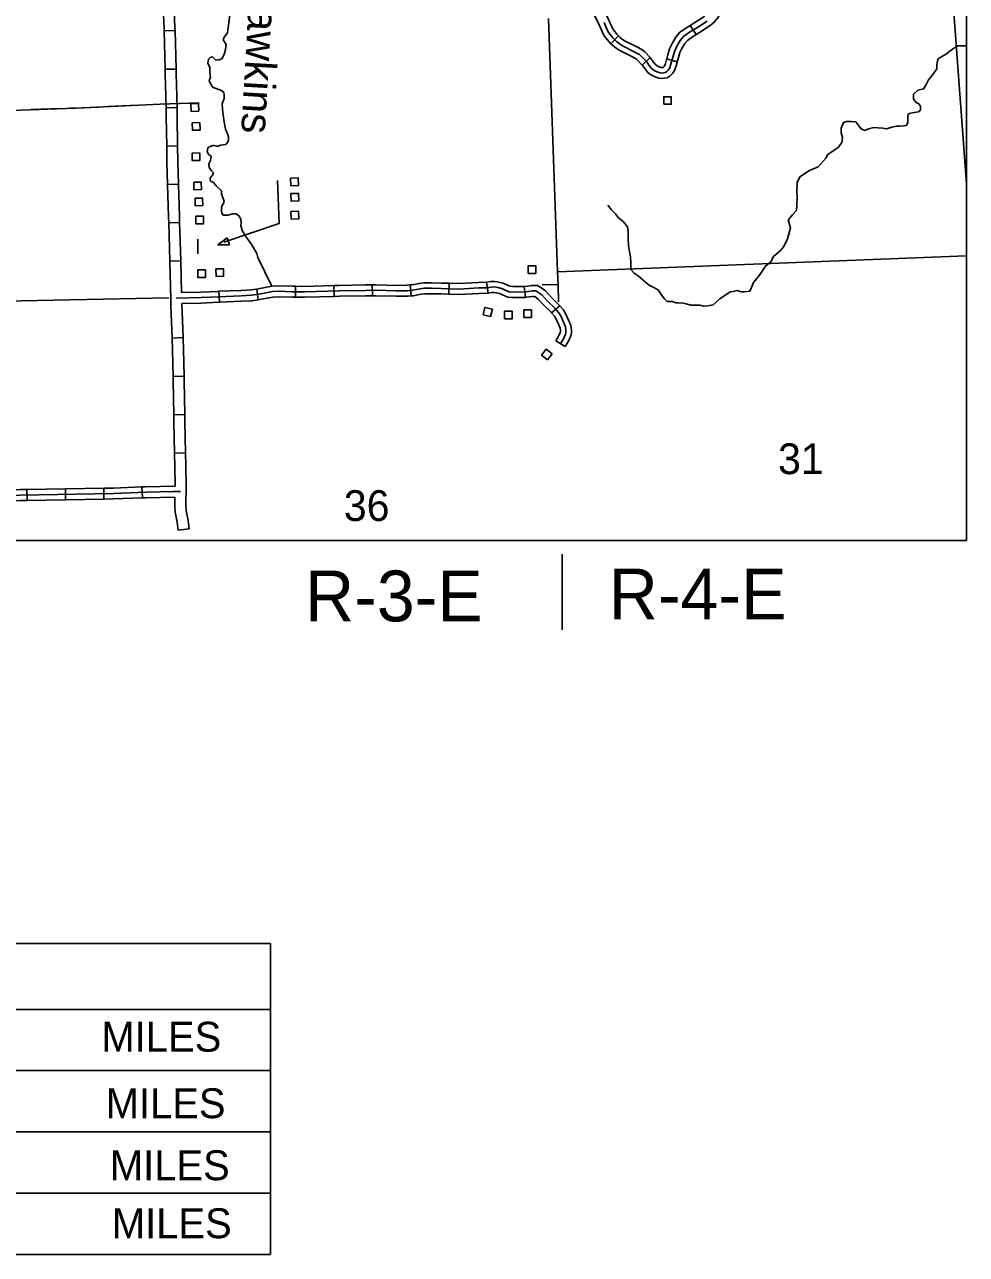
# Model space of a CAD drawing. Extents: x 155 to 3386, y 68 to 2138.
# Drawn here: x 1972.1 to 2342.2, y 68.1 to 551.2 of the extents above; entities that cross this region are included whole.
import ezdxf

# ---------------------------------------------------------------- set-up
doc = ezdxf.new("R2010")
doc.units = 0
for name, color, linetype in [('2', 7, 'Continuous'), ('3', 7, 'Continuous'), ('Default', 7, 'Continuous'), ('E_No Plot', 7, 'Continuous'), ('Level 32', 7, 'Continuous'), ('Level 35', 7, 'Continuous'), ('Level 4', 7, 'Continuous'), ('Level 43', 7, 'Continuous'), ('Level 5', 7, 'Continuous'), ('Level 56', 7, 'Continuous')]:
    doc.layers.add(name, color=color, linetype=linetype)

msp = doc.modelspace()

# ---------------------------------------------------------------- linework, layer by layer
at = {"layer": '2'}
msp.add_line((2183.32, 343.22), (2183.32, 313.48), dxfattribs=at)
at = {"layer": '3'}
for p, q in [((1431.26, 190.26), (2068.72, 190.26)), ((2068.72, 190.26), (2068.72, 68.06)), ((1431.26, 164.33), (2068.72, 164.33)), ((1431.26, 140.26), (2068.72, 140.26)), ((1431.26, 116.19), (2068.72, 116.19)), ((1431.26, 92.13), (2068.72, 92.13)), ((1431.26, 68.06), (2068.72, 68.06))]:
    msp.add_line(p, q, dxfattribs=at)
at = {"layer": 'Default'}
msp.add_lwpolyline([(1150.5, 1308.99), (2342.15, 1308.99), (2342.15, 348.58), (1150.5, 348.58)], close=True, dxfattribs=at)
at = {"layer": 'E_No Plot'}
msp.add_lwpolyline([(1150.5, 1308.99), (2342.15, 1308.99), (2342.15, 348.58), (1150.5, 348.58)], close=True, dxfattribs=at)
msp.add_lwpolyline([(1150.5, 1308.99), (2342.15, 1308.99), (2342.15, 348.58), (1150.5, 348.58)], close=True, dxfattribs=at)
at = {"layer": 'Level 32'}
for p, q in [((2233.63, 550.92), (2235.92, 547.3)), ((2031.17, 548.86), (2026.89, 548.75)), ((2205.49, 546.76), (2202.46, 543.73)), ((2217.87, 538.29), (2214.75, 535.35)), ((2224.42, 537.77), (2228.55, 536.63)), ((2031.58, 533.78), (2027.29, 533.67)), ((2031.95, 518.69), (2027.66, 518.59)), ((2032.18, 503.59), (2027.9, 503.53)), ((2032.52, 488.54), (2028.24, 488.41)), ((2032.98, 473.47), (2028.69, 473.33)), ((2033.46, 458.37), (2029.18, 458.27)), ((2138.86, 449.59), (2138.71, 445.31)), ((2153.54, 450), (2154.17, 445.76)), ((2048.42, 446.44), (2048.6, 442.15)), ((2063.26, 447.33), (2063.85, 443.09)), ((2078.56, 448.43), (2078.5, 444.14)), ((2093.54, 448.73), (2093.68, 444.45)), ((2108.67, 448.99), (2108.71, 444.71)), ((2123.59, 448.94), (2123.95, 444.67)), ((2168.32, 448.34), (2168.86, 444.09)), ((2182.39, 440.8), (2179.17, 437.97)), ((2034.34, 428.25), (2030.06, 428.08)), ((2184.53, 424.76), (2180.83, 426.94)), ((2034.73, 413.12), (2030.44, 413.04)), ((2034.99, 398.04), (2030.7, 397.96)), ((2035.29, 382.96), (2031, 382.87)), ((1973, 368.61), (1973.07, 364.32)), ((1988.08, 368.85), (1988.15, 364.56)), ((2003.17, 369.09), (2003.23, 364.8)), ((2018.19, 369.58), (2018.36, 365.3)), ((2036.69, 353.1), (2032.43, 352.61))]:
    msp.add_line(p, q, dxfattribs=at)
for points in [[(2026.89, 548.75), (2026.86, 549.77), (2026.28, 563.67), (2026.28, 563.66)], [(2031.17, 548.86), (2031.14, 549.92), (2030.55, 563.98), (2030.54, 564.09)], [(2243.15, 560.54), (2242.85, 559.93), (2240.88, 556.31), (2239.95, 555.17), (2238.93, 554.26), (2235.01, 551.79), (2233.63, 550.92)], [(2205.49, 546.76), (2204.82, 547.43), (2203.42, 549.2), (2202.85, 550.31), (2201.7, 552.95), (2200.38, 555.79), (2199.44, 557.19), (2198.57, 558.1), (2197.79, 558.63), (2196.16, 559.31), (2195.95, 559.36)], [(2247, 558.65), (2246.66, 557.97), (2244.46, 553.91), (2243.05, 552.19), (2241.51, 550.82), (2237.3, 548.17), (2235.92, 547.3)], [(2202.46, 543.73), (2201.61, 544.57), (2199.79, 546.87), (2198.97, 548.48), (2197.79, 551.2), (2196.64, 553.67), (2196.09, 554.49), (2195.78, 554.82), (2195.73, 554.85), (2194.88, 555.2), (2195.08, 555.16)], [(2240.22, 552.54), (2236.16, 549.98), (2233.38, 548.22), (2231.03, 546.61), (2229.72, 545), (2228.4, 542.81), (2227.52, 540.98), (2226.94, 538.85), (2226.42, 536.98), (2225.91, 535.26), (2225.44, 533.98), (2225, 533.36), (2224.41, 532.77), (2223.79, 532.37), (2223.06, 532.26), (2222.36, 532.19), (2221.81, 532.26), (2220.86, 532.55), (2219.51, 533.21), (2218.45, 533.95), (2217.46, 535.23), (2216.4, 536.73), (2214.28, 538.97), (2213.75, 539.43), (2211.92, 540.42), (2206.98, 542.91), (2205.78, 543.69), (2204.61, 544.61), (2203.21, 546), (2201.6, 548.03), (2200.91, 549.39), (2199.75, 552.08)], [(2233.63, 550.92), (2232.2, 550.01), (2229.57, 548.21), (2227.96, 546.24), (2226.51, 543.82), (2225.51, 541.73), (2224.87, 539.42), (2224.42, 537.77)], [(2027.29, 533.67), (2026.89, 548.75)], [(2031.58, 533.78), (2031.17, 548.86)], [(2217.87, 538.29), (2215.77, 540.52), (2214.98, 541.2), (2212.92, 542.32), (2208.05, 544.77), (2207.02, 545.44), (2206.03, 546.22), (2205.49, 546.76)], [(2235.92, 547.3), (2234.56, 546.43), (2232.5, 545.02), (2231.47, 543.77), (2230.29, 541.79), (2229.54, 540.22), (2229, 538.28), (2228.55, 536.63)], [(2214.75, 535.35), (2212.8, 537.42), (2212.53, 537.65), (2210.93, 538.52), (2205.91, 541.05), (2204.53, 541.95), (2203.18, 543), (2202.46, 543.73)], [(2228.55, 536.63), (2228.48, 536.4), (2227.94, 534.58), (2227.35, 532.98), (2226.64, 531.97), (2225.77, 531.1), (2224.56, 530.32), (2223.33, 530.14), (2222.33, 530.03), (2221.35, 530.16), (2220.07, 530.56), (2218.42, 531.36), (2216.95, 532.37), (2215.73, 533.95), (2214.73, 535.37), (2214.75, 535.35)], [(2224.42, 537.77), (2224.36, 537.57), (2223.88, 535.94), (2223.52, 534.99), (2223.35, 534.75), (2223.06, 534.45), (2223.01, 534.42), (2222.79, 534.39), (2222.39, 534.35), (2222.27, 534.36), (2221.65, 534.55), (2220.59, 535.07), (2219.94, 535.52), (2219.18, 536.5), (2218.06, 538.09), (2217.87, 538.29)], [(2027.66, 518.59), (2027.34, 531.86), (2027.29, 533.67)], [(2031.95, 518.69), (2031.63, 531.97), (2031.58, 533.78)], [(2027.9, 503.53), (2027.75, 514.99), (2027.66, 518.59)], [(2032.18, 503.59), (2032.03, 515.06), (2031.95, 518.69)], [(2028.24, 488.41), (2027.98, 497.18), (2027.9, 503.53)], [(2032.52, 488.54), (2032.26, 497.27), (2032.18, 503.59)], [(2028.69, 473.33), (2028.62, 475.77), (2028.24, 488.41)], [(2032.98, 473.47), (2032.9, 475.9), (2032.52, 488.54)], [(2029.18, 458.27), (2029.18, 458.4), (2028.69, 473.33)], [(2033.46, 458.37), (2033.46, 458.52), (2032.98, 473.47)], [(2029.5, 443.19), (2029.18, 458.27)], [(2033.73, 445.98), (2033.46, 458.37)], [(2138.86, 449.59), (2135.84, 449.7), (2131.96, 449.81), (2128.97, 449.77), (2127.22, 449.54), (2124.18, 448.99), (2123.59, 448.94)], [(2153.58, 450.01), (2150.41, 449.91), (2142.71, 449.46), (2138.86, 449.59)], [(2168.32, 448.34), (2168.3, 448.34), (2163.94, 448.31), (2162.96, 448.41), (2162.31, 448.64), (2160.13, 449.62), (2158.38, 450.08), (2156.82, 450.3), (2155.23, 450.25), (2153.54, 450)], [(2182.68, 425.85), (2183.83, 427.8), (2184.63, 429.65), (2184.77, 430.35), (2184.77, 431.04), (2184.6, 432.47), (2183.86, 434.32), (2182.75, 436.76), (2181.98, 438.01), (2180.49, 439.72), (2177.63, 442.51), (2175.33, 445.01), (2173.8, 446.13), (2172.96, 446.58), (2172.51, 446.62), (2171.54, 446.62), (2170.11, 446.41), (2168.44, 446.2), (2163.84, 446.16), (2162.48, 446.3), (2161.51, 446.65), (2159.42, 447.59), (2157.96, 447.98), (2156.7, 448.15), (2155.41, 448.11), (2153.78, 447.87), (2150.5, 447.77), (2142.74, 447.31), (2135.77, 447.56), (2131.94, 447.66), (2129.12, 447.63), (2127.56, 447.42), (2124.46, 446.86), (2122.4, 446.69), (2118.05, 446.65), (2110.04, 446.86), (2106.04, 446.83), (2095.69, 446.65), (2082.04, 446.23), (2077.31, 446.3), (2071.84, 446.44), (2069.51, 446.34), (2067.66, 446.02), (2064.14, 445.29), (2061.15, 444.87), (2057.21, 444.67), (2048.19, 444.28), (2041.44, 443.97), (2031.63, 443.8)], [(2048.42, 446.44), (2048.1, 446.42), (2041.37, 446.11), (2033.73, 445.98)], [(2063.26, 447.33), (2060.94, 447.01), (2057.11, 446.81), (2048.42, 446.44)], [(2078.56, 448.43), (2077.35, 448.45), (2071.82, 448.59), (2069.28, 448.47), (2067.26, 448.13), (2063.78, 447.41), (2063.26, 447.33)], [(2093.54, 448.73), (2082.03, 448.38), (2078.56, 448.43)], [(2108.67, 448.99), (2106.01, 448.97), (2095.64, 448.79), (2093.54, 448.73)], [(2108.71, 444.71), (2106.06, 444.68), (2095.74, 444.51), (2093.68, 444.45)], [(2123.59, 448.94), (2122.3, 448.83), (2118.07, 448.79), (2110.06, 449), (2108.67, 448.99)], [(2123.95, 444.67), (2122.5, 444.54), (2118.03, 444.51), (2110.02, 444.72), (2108.71, 444.71)], [(2138.71, 445.31), (2135.71, 445.42), (2131.93, 445.52), (2129.28, 445.49), (2127.89, 445.3), (2124.74, 444.73), (2123.95, 444.67)], [(2154.17, 445.76), (2153.97, 445.73), (2150.6, 445.63), (2142.76, 445.17), (2138.71, 445.31)], [(2168.86, 444.09), (2168.58, 444.06), (2163.74, 444.02), (2162.01, 444.2), (2160.71, 444.66), (2158.7, 445.56), (2157.54, 445.87), (2156.58, 446), (2155.6, 445.98), (2154.17, 445.76)], [(2182.39, 440.8), (2182.04, 441.19), (2179.17, 444), (2176.77, 446.62), (2174.95, 447.95), (2173.58, 448.68), (2172.59, 448.76), (2171.38, 448.76), (2169.82, 448.53), (2168.32, 448.34)], [(2030.06, 428.08), (2029.56, 440.75), (2029.5, 443.19)], [(2048.6, 442.15), (2048.29, 442.14), (2041.51, 441.83), (2033.81, 441.69)], [(2034.34, 428.25), (2033.81, 441.69)], [(2063.85, 443.09), (2061.35, 442.74), (2057.32, 442.53), (2048.6, 442.15)], [(2078.5, 444.14), (2077.26, 444.16), (2071.86, 444.3), (2069.73, 444.2), (2068.06, 443.92), (2064.51, 443.18), (2063.85, 443.09)], [(2093.68, 444.45), (2082.06, 444.09), (2078.5, 444.14)], [(2179.17, 437.97), (2178.93, 438.24), (2176.09, 441.01), (2173.9, 443.41), (2172.65, 444.31), (2172.36, 444.47), (2171.69, 444.47), (2170.4, 444.28), (2168.86, 444.09)], [(2184.53, 424.76), (2185.74, 426.83), (2186.69, 429.01), (2186.91, 430.13), (2186.91, 431.17), (2186.69, 433), (2185.84, 435.16), (2184.65, 437.76), (2183.72, 439.29), (2182.39, 440.8)], [(2180.83, 426.94), (2181.92, 428.78), (2182.57, 430.29), (2182.63, 430.56), (2182.63, 430.91), (2182.5, 431.94), (2181.89, 433.48), (2180.85, 435.75), (2180.25, 436.74), (2179.17, 437.97)], [(2030.44, 413.04), (2030.24, 423.33), (2030.06, 428.08)], [(2034.73, 413.12), (2034.53, 423.45), (2034.34, 428.25)], [(2030.7, 397.96), (2030.47, 411.3), (2030.44, 413.04)], [(2034.99, 398.04), (2034.76, 411.37), (2034.73, 413.12)], [(2031, 382.87), (2030.75, 395.02), (2030.7, 397.96)], [(2035.29, 382.96), (2035.04, 395.1), (2034.99, 398.04)], [(2031.26, 369.91), (2031.11, 377.65), (2031, 382.87)], [(2035.5, 367.78), (2035.55, 369.61), (2035.39, 377.73), (2035.29, 382.96)], [(2033.36, 367.8), (2030.52, 367.75), (2019.66, 367.5), (2007, 367.01), (1970.32, 366.42), (1943.61, 365.39), (1901.56, 364.09), (1856.6, 362.28), (1834.02, 361.76), (1809.57, 360.99), (1766.1, 360.08), (1696.04, 358.14), (1659.82, 357.18)], [(1973, 368.61), (1970.27, 368.57), (1957.87, 368.09)], [(1988.08, 368.85), (1973, 368.61)], [(2003.17, 369.09), (1988.08, 368.85)], [(2018.19, 369.58), (2006.95, 369.15), (2003.17, 369.09)], [(2031.26, 369.91), (2019.59, 369.64), (2018.19, 369.58)], [(2036.69, 353.1), (2036.31, 356.42), (2035.53, 360.3), (2035.4, 362.41), (2035.42, 364.69), (2035.5, 367.78)], [(1973.07, 364.32), (1970.38, 364.28), (1958.04, 363.8)], [(1988.15, 364.56), (1973.07, 364.32)], [(2003.23, 364.8), (1988.15, 364.56)], [(2018.36, 365.3), (2007.06, 364.86), (2003.23, 364.8)], [(2031.14, 365.62), (2019.72, 365.35), (2018.36, 365.3)], [(2032.43, 352.61), (2032.08, 355.76), (2031.28, 359.73), (2031.11, 362.3), (2031.14, 365.62)]]:
    msp.add_lwpolyline(points, dxfattribs=at)
at = {"layer": 'Level 35'}
for points in [[(2053.34, 560.11), (2051.79, 547.94), (2051.59, 547.63), (2050.43, 546.32), (2050.07, 545.31), (2051.29, 543.38), (2051.03, 541.51), (2050.48, 539.49), (2049.57, 537.77), (2048.05, 537.22), (2047.04, 537.37), (2045.88, 538.53), (2044.97, 538.33), (2044.37, 537.72), (2044.06, 536.11), (2044.82, 534.39), (2044.87, 532.72), (2044.92, 531.2), (2045.07, 530.63), (2044.62, 529.12), (2044.92, 528.36), (2045.83, 526.89), (2046.44, 526.39), (2046.44, 526.39), (2046.54, 526.39), (2048.41, 525.73), (2049.62, 525.28), (2050.33, 524.57), (2050.48, 523.46), (2050.48, 522.09), (2050.07, 521.28), (2049.72, 520.12), (2049.77, 518.05), (2050.07, 515.83), (2050.53, 512.94), (2050.98, 510.11), (2051.79, 508.35), (2052.14, 507.06), (2052.19, 505.8), (2051.84, 504.89), (2051.39, 504.43), (2050.98, 504.18), (2050.07, 504.03), (2049.01, 503.88), (2048.1, 503.47), (2047.55, 503.47), (2046.54, 503.73), (2046.03, 503.73), (2044.36, 503.02), (2044.06, 502.66), (2043.76, 501.25), (2044.36, 500.34), (2045.32, 499.48), (2045.22, 498.62), (2045.07, 497.86), (2044.42, 496.5), (2044.57, 495.13), (2045.48, 493.77), (2046.28, 492.96), (2045.93, 491.95), (2045.37, 491.5), (2045.02, 490.84), (2045.02, 490.23), (2045.12, 489.78), (2045.48, 489.63), (2046.28, 489.17), (2047.29, 487.91), (2049.47, 485.99), (2049.47, 484.67), (2050.43, 481.87), (2050.17, 480.91), (2049.72, 480.2), (2049.47, 479.44), (2049.47, 477.93), (2049.47, 477.87), (2049.57, 477.12), (2050.12, 476.41), (2050.88, 476.31), (2051.89, 476.41)], [(2342.15, 542.95), (2341.56, 542.95), (2340.22, 542.95), (2338.66, 542.88), (2336.74, 541.54), (2333.99, 539.46), (2331.18, 537.91), (2330.73, 537.02), (2330.58, 535.46), (2330.51, 533.9), (2329.62, 532.56), (2328.51, 531.16), (2327.32, 529.6), (2326.21, 527.45), (2325.32, 525.96), (2323.09, 525.44), (2321.39, 523.96), (2321.31, 521.88), (2322.57, 520.55), (2323.39, 520.18), (2324.06, 519.21), (2324.13, 517.65), (2323.39, 516.99), (2321.68, 516.76), (2319.61, 516.32), (2319.16, 515.72), (2319.16, 515.5), (2319.16, 514.17), (2319.16, 512.68), (2318.5, 511.64), (2317.38, 511.42), (2316.05, 511.35), (2314.71, 511.35), (2312.86, 510.98), (2310.78, 510.23), (2309.3, 510.53), (2307.3, 510.68), (2305.74, 510.83), (2303.74, 510.31), (2302.18, 509.57), (2300.85, 510.31), (2299.44, 511.94), (2298.7, 512.98), (2296.92, 513.2), (2295.06, 513.2), (2293.88, 512.83), (2292.91, 510.53), (2292.91, 508.75), (2293.43, 506.82), (2293.14, 504.97), (2291.73, 502.89), (2289.8, 501.7), (2287.65, 500.22), (2286.91, 498.74), (2283.94, 495.32), (2280.46, 493.91), (2276.75, 491.39), (2275.71, 489.17), (2275.56, 485.23), (2275.64, 483.6), (2275.56, 480.12), (2275.41, 478.26), (2273.78, 476.48), (2272.15, 474.55), (2273.04, 471.36), (2271.86, 467.13), (2270.37, 464.02), (2269.11, 462.46), (2266.22, 459.94), (2265.4, 458.16), (2263.18, 456.3), (2260.88, 452.81), (2259.18, 450.74), (2258.51, 449.92), (2257.69, 447.99), (2257.1, 446.51), (2254.88, 446.21), (2253.69, 446.29), (2252.13, 446.81), (2250.5, 446.43), (2249.31, 446.21), (2245.31, 443.47), (2242.64, 441.09), (2240.49, 440.72), (2238.86, 440.65), (2237.45, 440.95), (2235.52, 440.95), (2233.67, 440.95), (2232.04, 441.54)], [(2232.04, 441.54), (2230.85, 441.84), (2228.92, 441.91), (2228.03, 441.98), (2226.7, 442.43), (2224.62, 442.5), (2223.36, 443.62), (2221.95, 445.54), (2221.21, 446.88), (2219.28, 447.92), (2217.43, 448.81), (2216.17, 449.92), (2213.2, 452.52), (2211.57, 453.63), (2210.31, 454.97), (2210.31, 456.23), (2210.24, 457.71), (2210.16, 459.94), (2209.35, 464.17), (2209.27, 467.43), (2209.27, 470.1), (2208.98, 471.73), (2207.42, 473.74), (2205.34, 475.44), (2204.31, 476.85), (2202.6, 478.63), (2201.27, 480.34)], [(2051.89, 476.41), (2053.71, 476.91), (2055.17, 476.91), (2056.29, 476.11), (2056.99, 474.79), (2057.2, 473.38), (2057.09, 472.26), (2057.6, 470.29), (2059.01, 467.97), (2061.39, 464.71), (2063.31, 461.33), (2063.74, 459.74), (2069.28, 448.47)]]:
    msp.add_lwpolyline(points, dxfattribs=at)
at = {"layer": 'Level 4'}
msp.add_lwpolyline([(2177.87, 553.68), (2181.49, 454.04), (2181.67, 449.15), (2181.92, 442.29)], dxfattribs=at)
at = {"layer": 'Level 43'}
for points in [[(2040.67, 520.48), (2025.37, 519.96), (1992.1, 518.45), (1963.2, 517.4)], [(1986.03, 518.23), (1974.73, 517.82)], [(2001.1, 518.86), (1992.1, 518.45), (1989.8, 518.37)], [(2016.17, 519.54), (2004.87, 519.03)]]:
    msp.add_lwpolyline(points, dxfattribs=at)
at = {"layer": 'Level 5'}
for points in [[(2334.18, 596.75), (2342.15, 488.68)], [(2181.49, 454.04), (2342.15, 460.35)], [(2175.45, 448.93), (2181.67, 449.15)], [(1880.26, 440.83), (2028.7, 443.92)]]:
    msp.add_lwpolyline(points, dxfattribs=at)
at = {"layer": 'Level 56'}
for points in [[(2223.21, 519.94), (2223.21, 522.92), (2226.19, 522.92), (2226.19, 519.94)], [(2037.42, 520.15), (2040.39, 520.22), (2040.47, 517.24), (2037.49, 517.16)], [(2037.94, 512.7), (2040.92, 512.77), (2040.99, 509.79), (2038.02, 509.71)], [(2037.9, 500.77), (2040.87, 500.84), (2040.95, 497.86), (2037.97, 497.79)], [(2038.52, 489.3), (2041.49, 489.37), (2041.56, 486.39), (2038.59, 486.32)], [(2076.6, 490.91), (2079.57, 490.98), (2079.64, 488), (2076.67, 487.92)], [(2076.74, 484.86), (2079.71, 484.93), (2079.78, 481.95), (2076.81, 481.88)], [(2039.04, 483.02), (2042.01, 483.09), (2042.08, 480.11), (2039.11, 480.04)], [(2039.34, 475.91), (2042.31, 475.98), (2042.39, 473), (2039.41, 472.93)], [(2076.74, 477.83), (2079.71, 477.9), (2079.78, 474.92), (2076.81, 474.85)], [(2052.63, 464.67), (2051.7, 467.43), (2048.02, 464.65)], [(2040.12, 454.83), (2043.09, 454.9), (2043.16, 451.92), (2040.19, 451.85)], [(2047.23, 455.25), (2050.21, 455.32), (2050.28, 452.34), (2047.31, 452.27)], [(2169.96, 453.48), (2169.96, 456.46), (2172.94, 456.46), (2172.94, 453.48)], [(2152.23, 437.27), (2152.98, 440.15), (2155.87, 439.41), (2155.12, 436.53)], [(2160.69, 435.66), (2160.69, 438.63), (2163.67, 438.63), (2163.67, 435.66)], [(2168.23, 436.16), (2168.23, 439.13), (2171.21, 439.13), (2171.21, 436.16)], [(2179.38, 421.88), (2177.53, 419.56), (2175.19, 421.42), (2177.05, 423.74)]]:
    msp.add_lwpolyline(points, close=True, dxfattribs=at)
for points in [[(2050.41, 465.78), (2072.06, 473.09), (2071.45, 489.96)], [(2040.15, 466.9), (2040.15, 461.14)]]:
    msp.add_lwpolyline(points, dxfattribs=at)

# ---------------------------------------------------------------- texts
at = {"layer": '2'}
for s, p in [('R-3-E', (2082.26, 316.75)), ('R-4-E', (2201.6, 317.51))]:
    msp.add_text(s, height=20, dxfattribs=at).set_placement(p)
at = {"layer": '3'}
for p in [(2002.24, 147.7), (2003.9, 121.58), (2005.56, 97.21), (2006.34, 74.42)]:
    msp.add_text('MILES', height=11.741, dxfattribs=at).set_placement(p)
at = {"layer": 'Level 35'}
msp.add_text('Hawkins', height=12.069, rotation=266.7062, dxfattribs=at).set_placement((2060.68, 569.62))
at = {"layer": 'Level 5'}
for s, p in [('31', (2268.13, 374.62)), ('36', (2097.51, 356.22))]:
    msp.add_text(s, height=12.069, dxfattribs=at).set_placement(p)

doc.saveas('drawing.dxf')
